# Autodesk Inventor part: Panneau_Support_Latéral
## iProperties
Created: 2009-02
Part Number: Panneau_Support_Latéral
Document SubType Name: Sheet Metal
Designer: Alex_Cyril
Author: Alex_Cyril
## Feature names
1. Extrusion1
2. Perçage1 [Hole]
3. Chanfrein de coin1
4. Chanfrein de coin2
5. Perçage2 [Hole]
6. Perçage3 [Hole]
7. Plaque1
8. Pli1
9. Plaque2
10. Pli2
11. Couper1
12. Couper2
13. Couper3
